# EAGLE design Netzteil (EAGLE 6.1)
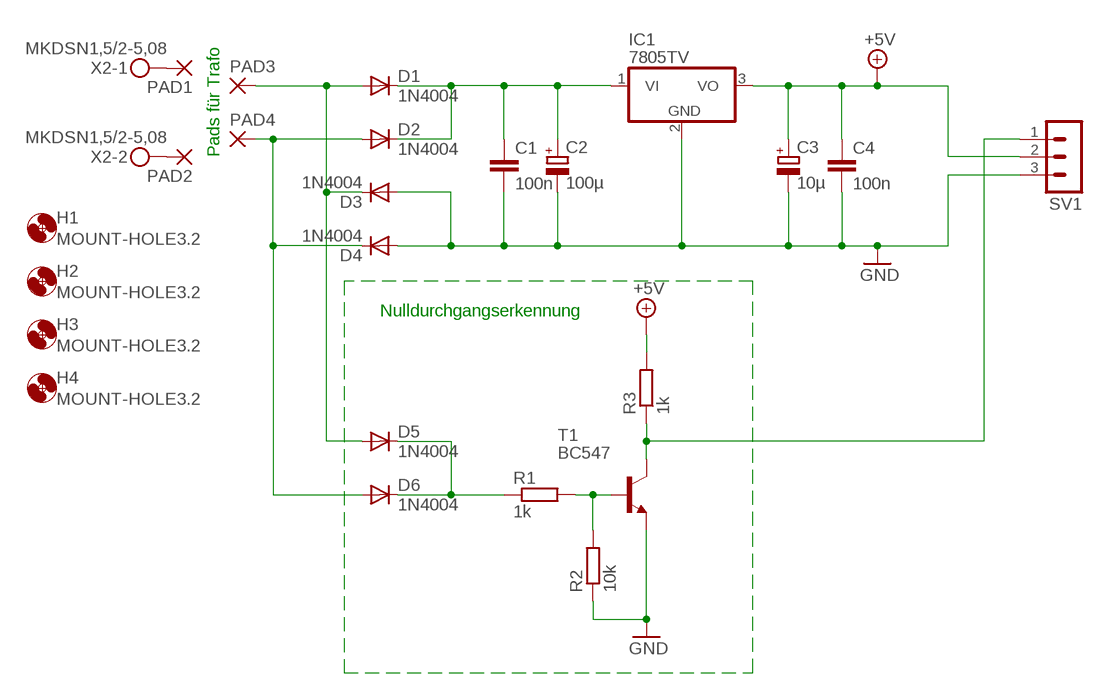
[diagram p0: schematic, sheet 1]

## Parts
C1  100n  C-EU025-025X050  [C025-025X050]
C2  100µ  CPOL-EUE3.5-8  [E3,5-8]
C3  10µ  CPOL-EUE2.5-5  [E2,5-5]
C4  100n  C-EU025-025X050  [C025-025X050]
D1  1N4004  [DO41-10]
D2  1N4004  [DO41-10]
D3  1N4004  [DO41-10]
D4  1N4004  [DO41-10]
D5  1N4004  [DO41-10]
D6  1N4004  [DO41-10]
H1  MOUNT-HOLE3.2  [3,2]
H2  MOUNT-HOLE3.2  [3,2]
H3  MOUNT-HOLE3.2  [3,2]
H4  MOUNT-HOLE3.2  [3,2]
IC1  7805TV  [TO220V]
PAD1  3,81/1,1  [3,81/1,1]
PAD2  3,81/1,1  [3,81/1,1]
PAD3  3,81/1,1  [3,81/1,1]
PAD4  3,81/1,1  [3,81/1,1]
R1  1k  R-EU_0204/7  [0204/7]
R2  10k  R-EU_0204/7  [0204/7]
R3  1k  R-EU_0204/7  [0204/7]
SV1  MA03-1  [MA03-1]
T1  BC547  [TO92]
X2  MKDSN1,5/2-5,08  [MKDSN1,5/2-5,08]

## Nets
+5V: C3.+ C4.1 IC1.3(VO) R3.2 SV1.2
GND: C1.2 C2.- C3.- C4.2 D3.A D4.A IC1.2(GND) R2.1 SV1.3 T1.1(E)
N$1: D1.A D3.C D5.A PAD3.1(P)
N$2: D2.A D4.C D6.A PAD4.1(P)
N$3: D5.C D6.C R1.1
N$4: R1.2 R2.2 T1.2(B)
N$5: PAD1.1(P) X2.1
N$6: C1.1 C2.+ D1.C D2.C IC1.1(VI)
N$7: PAD2.1(P) X2.2
N$39: R3.1 SV1.1 T1.3(C)

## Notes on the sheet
- Pads für Trafo
- Nulldurchgangserkennung

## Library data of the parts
C1 C4 = resistor:C-EU: CAPACITOR, European symbol
C2 = resistor:CPOL-EU: POLARIZED CAPACITOR, European symbol
C3 = rcl:CPOL-EU: POLARIZED CAPACITOR, European symbol
D1-D6 = diode:1N4004: DIODE
H1-H4 = holes:MOUNT-HOLE: MOUNTING HOLE with drill center marker
IC1 = linear:78*: Positive VOLTAGE REGULATOR Source: http://cache.national.com/ds/LM/LM78L05.pdf http://www.fairchildsemi.com/ds/LM/LM7805.pdf
PAD1-PAD4 = wirepad:3,81/1,1: THROUGH-HOLE PAD
R1-R3 = resistor:R-EU_: RESISTOR, European symbol
SV1 = con-lstb:MA03-1: PIN HEADER
T1 = transistor:BC547: NPN TRANSISTOR
X2 = con-phoenix-508:MKDSN1,5/2-5,08: MKDSN 1,5/ 2-5,08 Printklemme

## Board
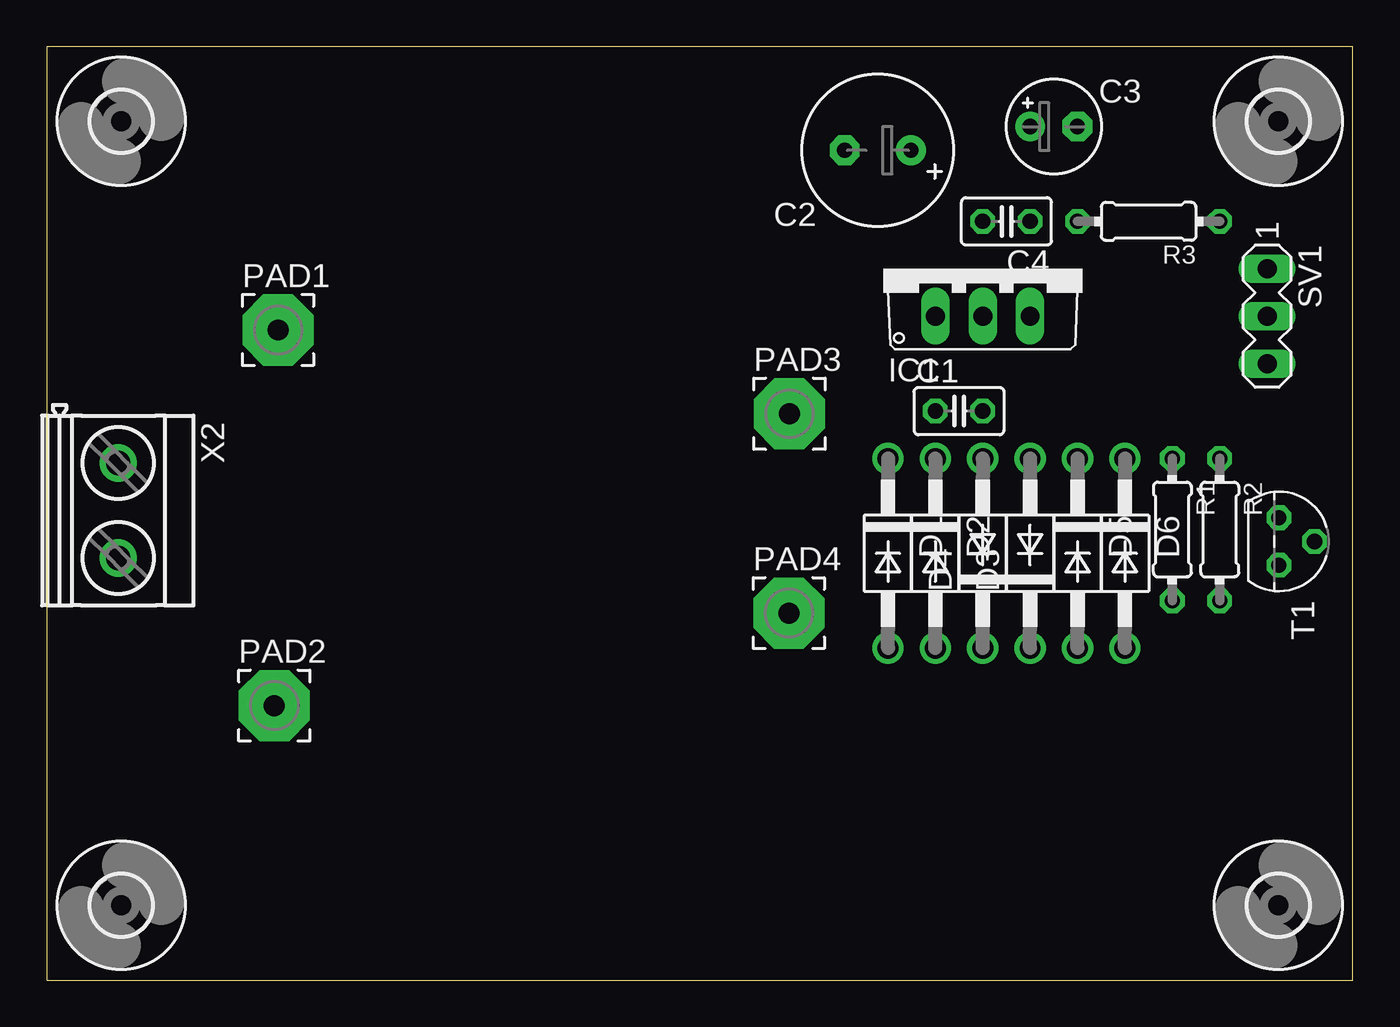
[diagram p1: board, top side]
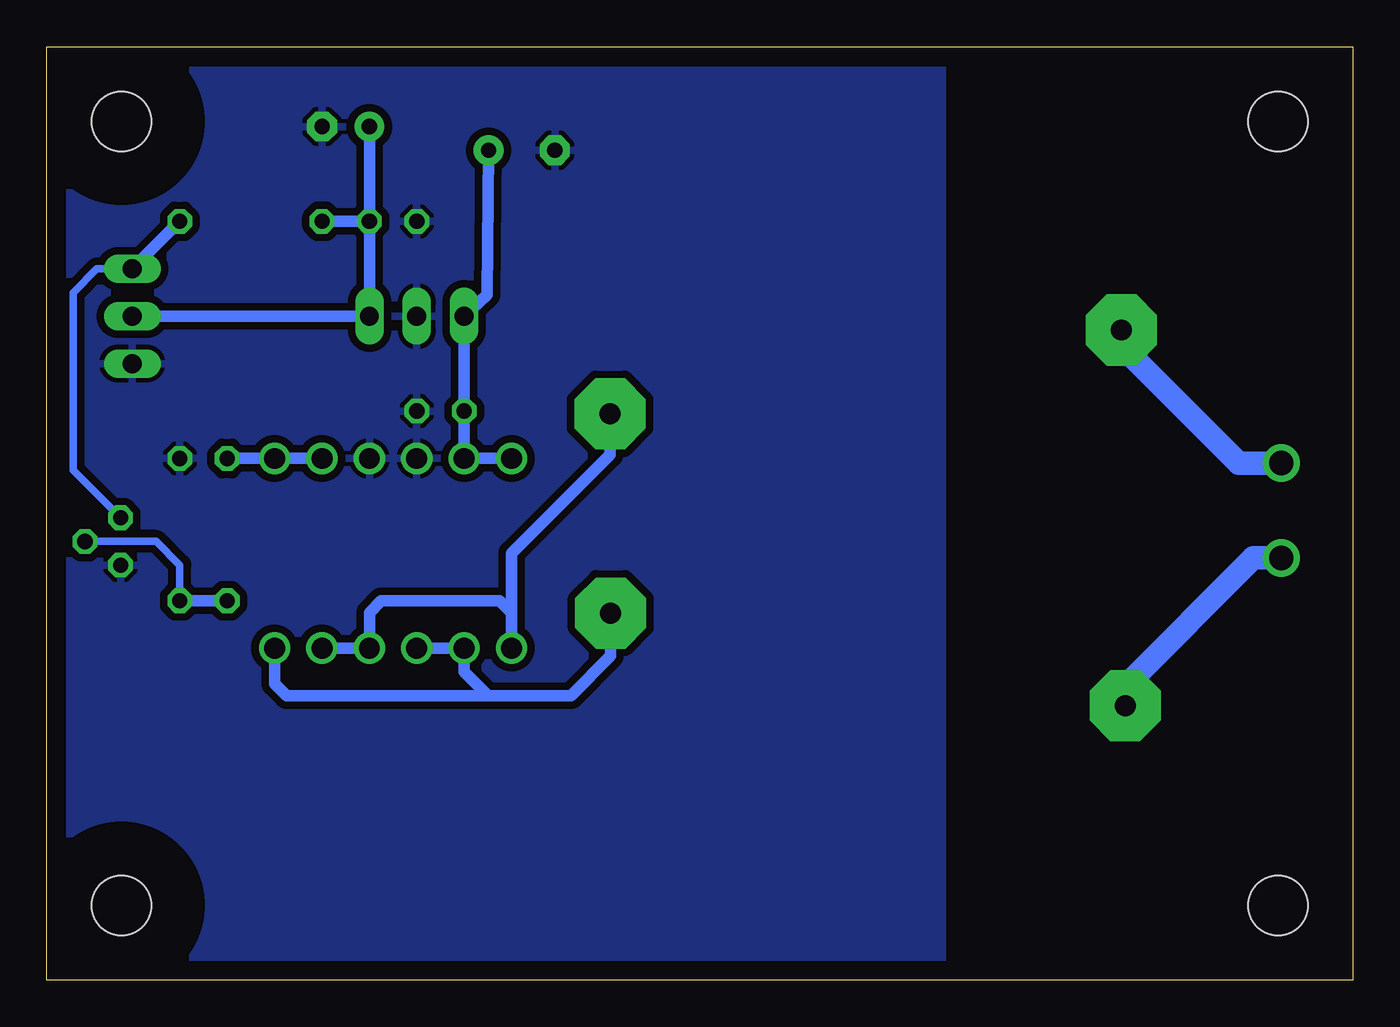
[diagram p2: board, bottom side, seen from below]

Size 70 x 50 mm. Coordinates in mm from the lower left corner, seen from the top.
Outline: 0,0 70,0 70,50 0,50 0,0
Copper layers (1*16): Top 0.035mm / dielectric 1.5mm / Bottom 0.035mm
Design rules "default": minimum track width 10mil, minimum drill 24mil, track to track 8mil, track to pad 8mil, pad to pad 8mil, via to via 8mil, smd to smd 8mil, copper to edge 40mil, drill to drill 8mil, minimum pad ring 10mil, minimum via ring 8mil, stop-mask expansion 4mil, vias tented up to drill 0mil, thermal gap 10mil

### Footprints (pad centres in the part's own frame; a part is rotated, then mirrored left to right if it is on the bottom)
C025-025X050 = drill 0.813 octagon: 1 -1.27,0; 2 1.27,0
E3,5-8 = drill 0.813 pad 1.6 round: + -1.778,0 | drill 0.813 pad 1.6 octagon: - 1.778,0
E2,5-5 = drill 0.813 pad 1.6 round: + -1.27,0 | drill 0.813 pad 1.6 octagon: - 1.27,0
DO41-10 = drill 1.118 round: A 5.08,0; C -5.08,0
3,2 = hole 3.2: 0,0
TO220V = drill 1.016 long: 1 -2.54,-2.54; 2 0,-2.54; 3 2.54,-2.54
3,81/1,1 = drill 1.118 pad 3.81 octagon: 1 0,0
0204/7 = drill 0.813 octagon: 1 -3.81,0; 2 3.81,0
MA03-1 = drill 1.016 long: 1 -2.54,0; 2 0,0; 3 2.54,0
TO92 = drill 0.813 octagon: 1 1.27,0; 2 0,1.905; 3 -1.27,0
MKDSN1,5/2-5,08 = drill 1.3 pad 2 round: 1 -2.561,0.025; 2 2.519,0.025

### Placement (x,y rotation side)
C1  48.9,30.48 0 top
C2  44.55,44.45 180 top
C3  53.98,45.72 0 top
C4  51.44,40.64 180 top
D1  45.09,22.86 270 top
D2  47.62,22.86 270 top
D3  52.7,22.86 90 top
D4  50.16,22.86 90 top
D5  55.24,22.86 270 top
D6  57.78,22.86 270 top
H1  4,4 0 top
H2  4,46 0 top
H3  66,4 0 top
H4  66,46 0 top
IC1  50.16,38.1 0 top
PAD1  12.4,34.82 0 top
PAD2  12.2,14.7 0 top
PAD3  39.8,30.34 0 top
PAD4  39.77,19.66 0 top
R1  60.33,24.13 270 top
R2  62.87,24.13 270 top
R3  59.05,40.64 180 top
SV1  65.41,35.56 270 top
T1  66.04,23.5 270 top
X2  3.81,25.13 270 top

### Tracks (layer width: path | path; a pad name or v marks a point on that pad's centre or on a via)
+5V
  Bottom 0.61: SV1.2 IC1.3 C4.1 | C4.1 R3.2 | C4.1 C3.+
GND
  pour Bottom (isolate 0.406): 22,49 22,1 69,1 69,48 68,49
N$1
  Bottom 0.61: PAD3.1 39.8,28.14 45.09,22.86 D1.A 45.09,19.68 45.72,20.32 52.07,20.32 52.7,19.68 D3.C D5.A
N$2
  Bottom 0.61: PAD4.1 39.77,17.38 41.91,15.24 45.72,15.24 46.35,15.24 | 46.35,15.24 47.62,16.51 D2.A D4.C | D6.A 57.78,15.88 57.15,15.24 46.35,15.24
N$3
  Bottom 0.61: D5.C D6.C R1.1
N$4
  Bottom 0.406: T1.2 64.14,23.5 62.87,22.23 R2.2
  Bottom 0.61: R1.2 R2.2
N$5
  Bottom 1.27: PAD1.1 12.4,33.99 6.1,27.69 X2.1
N$6
  Bottom 0.61: C2.+ 46.39,36.7 IC1.1 C1.1 D2.C D1.C
N$7
  Bottom 1.27: X2.2 5.33,22.61 12.2,15.74 PAD2.1
N$39
  Bottom 0.406: SV1.1 67.31,38.1 68.58,36.83 68.58,27.3 T1.3
  Bottom 0.61: SV1.1 R3.1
